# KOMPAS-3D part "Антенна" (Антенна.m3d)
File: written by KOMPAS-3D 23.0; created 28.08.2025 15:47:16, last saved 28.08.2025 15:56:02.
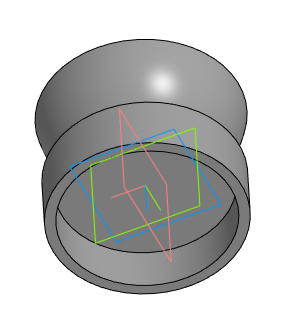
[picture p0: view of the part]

Document properties: Автор: Inspektor_Kot; Полное имя файла: I:\Autodesk Inventor Projects\ИМ-ИТ ЦД\Вариант 2\Колпак.m3d

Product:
- Part/product: Антенна
    Масса: 0.726017

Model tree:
1. Эскиз:1  (with: Элемент вращения:1)  (labels: I:\Autodesk Inventor Projects\ИМ-ИТ ЦД\Вариант 2\Спутник.a3d)
2. Элемент выдавливания:1  (with: Элемент вращения:1)  (labels: I:\Autodesk Inventor Projects\ИМ-ИТ ЦД\Вариант 2\Спутник.a3d)
     Расстояние 2 = 21
3. Эскиз:3  (with: Элемент выдавливания:1)
4. Элемент выдавливания:2
     Расстояние 1 = 5
5. Эскиз:4  (with: Элемент выдавливания:2)
6. Элемент вращения:2
     Угол 1 = 360

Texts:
  Угловой размер с обрывом
  Линейный размер с обрывом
